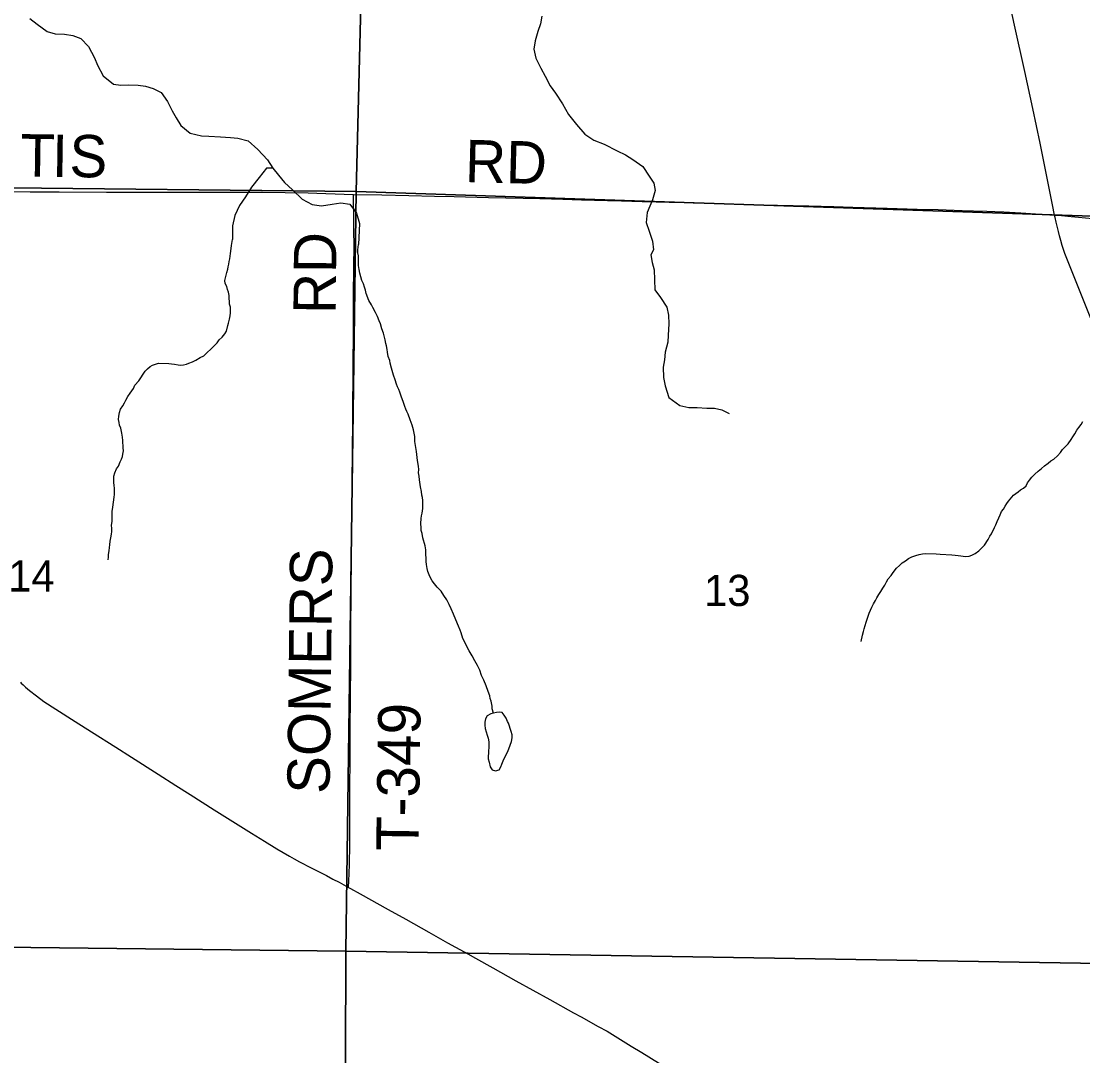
# Model space of a CAD drawing. Extents: x -8.8 to 41.4, y 0 to 34.6.
# Drawn here: x 3.891 to 5.315, y 15.426 to 16.815 of the extents above; entities that cross this region are included whole.
import ezdxf

# ---------------------------------------------------------------- set-up
doc = ezdxf.new("R2010")
doc.units = 0
for name, color, linetype in [('GM_X_Corporation', 7, 'Continuous'), ('GM_X_County_Road', 7, 'Continuous'), ('GM_X_Minor_Lake', 7, 'Continuous'), ('GM_X_Minor_River', 7, 'Continuous'), ('GM_X_Section_Text', 7, 'Continuous'), ('GM_X_Township_Road', 7, 'Continuous'), ('GM_X_Township_Road_Text', 7, 'Continuous'), ('GM_X_Township_Text', 7, 'Continuous')]:
    doc.layers.add(name, color=color, linetype=linetype)

msp = doc.modelspace()

# ---------------------------------------------------------------- linework, layer by layer
at = {"layer": 'GM_X_Corporation'}
for points in [[(3.3365, 17.5869), (4.3651, 17.5696), (4.3404, 16.586), (3.3269, 16.5968)], [(5.3707, 17.5614), (5.354, 16.5519), (4.3404, 16.586), (4.3651, 17.5696)], [(3.3269, 16.5968), (4.3404, 16.586), (4.3264, 15.5667), (3.3275, 15.5783)], [(4.3404, 16.586), (5.354, 16.5519), (5.3394, 15.5503), (4.3264, 15.5667)], [(4.3264, 15.5667), (4.3237, 14.5538), (3.3268, 14.5649), (3.3275, 15.5783)], [(4.3264, 15.5667), (5.3394, 15.5503), (5.3392, 15.4586), (5.3337, 14.5401), (4.3237, 14.5538)]]:
    msp.add_lwpolyline(points, close=True, dxfattribs=at)
at = {"layer": 'GM_X_County_Road'}
for points in [[(5.332, 16.4001), (5.2912, 16.5029), (5.2875, 16.5136), (5.2856, 16.5202), (5.2839, 16.5266), (5.2824, 16.5325), (5.2811, 16.5379), (5.2795, 16.5447), (5.278, 16.5511), (5.2773, 16.5543), (5.2745, 16.5684), (5.2578, 16.6509), (5.2482, 16.6973), (5.2372, 16.7472), (5.2236, 16.8095), (5.2113, 16.8654)], [(3.8697, 16.5859), (3.9034, 16.5858), (3.9419, 16.5857), (4.0058, 16.5853), (4.0326, 16.5853), (4.0679, 16.5854), (4.1058, 16.5853), (4.1306, 16.5853), (4.1561, 16.5853), (4.1694, 16.5854), (4.1846, 16.5853), (4.2144, 16.5851), (4.2759, 16.5841), (4.2877, 16.5837), (4.3243, 16.5825), (4.3369, 16.5822), (4.3747, 16.5815), (4.4113, 16.5808), (4.4454, 16.58), (4.4721, 16.5793), (4.487, 16.5791), (4.5181, 16.578), (4.5647, 16.577), (4.587, 16.5765), (4.6175, 16.5757), (4.6429, 16.575), (4.6777, 16.5741), (4.6963, 16.5737), (4.7242, 16.5728), (4.7429, 16.5722), (4.7603, 16.5718), (4.7832, 16.5711), (4.7926, 16.5709), (4.818, 16.5703), (4.8646, 16.5688), (4.9056, 16.5677), (4.9478, 16.5667), (4.9814, 16.5658), (5.0068, 16.5651), (5.0528, 16.5637), (5.0931, 16.5625), (5.1211, 16.5617), (5.1534, 16.5606), (5.1684, 16.5601), (5.1863, 16.5598), (5.1973, 16.5594), (5.2092, 16.5589), (5.232, 16.5574), (5.2585, 16.5557), (5.2773, 16.5543), (5.2867, 16.5537), (5.2997, 16.5526), (5.3096, 16.5517), (5.328, 16.55)], [(3.8901, 15.9275), (3.8913, 15.9263), (3.8936, 15.9241), (3.897, 15.9211), (3.9024, 15.9164), (3.9117, 15.9092), (3.9217, 15.9019), (3.9377, 15.8913), (3.9634, 15.8749), (3.9854, 15.8609), (4.018, 15.8403), (4.0389, 15.8269), (4.0751, 15.804), (4.0987, 15.7889), (4.1176, 15.7769), (4.1502, 15.7564), (4.2002, 15.7251), (4.2176, 15.7142), (4.2339, 15.7041), (4.251, 15.6941), (4.2575, 15.6904), (4.2646, 15.6866), (4.28, 15.6785), (4.2883, 15.6743), (4.3005, 15.668), (4.3093, 15.6634), (4.3175, 15.6591), (4.3303, 15.6523), (4.3329, 15.6509), (4.346, 15.6438), (4.3834, 15.6228), (4.4072, 15.6094), (4.4381, 15.592), (4.463, 15.578), (4.4901, 15.5629), (4.5005, 15.5572), (4.5238, 15.5442), (4.5548, 15.527), (4.6004, 15.5016), (4.6319, 15.4841), (4.6422, 15.4785), (4.6651, 15.4658), (4.677, 15.4591), (4.7093, 15.4393), (4.7236, 15.4306), (4.7592, 15.4089)]]:
    msp.add_lwpolyline(points, dxfattribs=at)
at = {"layer": 'GM_X_Minor_Lake'}
for points in [[(4.5363, 15.8871), (4.5331, 15.8874), (4.5286, 15.8868), (4.5248, 15.8861), (4.5209, 15.8851), (4.5163, 15.8826), (4.5139, 15.8785), (4.513, 15.8739), (4.5129, 15.8698), (4.5136, 15.8656), (4.5163, 15.8564), (4.5174, 15.8525), (4.5184, 15.8476), (4.5186, 15.8434), (4.5185, 15.8396), (4.518, 15.8358), (4.5177, 15.8248), (4.5187, 15.8202), (4.5204, 15.8141), (4.523, 15.8102), (4.5275, 15.8086), (4.5325, 15.8099), (4.5345, 15.8141), (4.5357, 15.8178), (4.5377, 15.8219), (4.5394, 15.8261), (4.5434, 15.8336), (4.5454, 15.8384), (4.5471, 15.843), (4.5487, 15.8482), (4.5496, 15.8531), (4.5497, 15.8569), (4.5484, 15.8614), (4.5447, 15.8727)], [(4.5447, 15.8727), (4.5434, 15.875), (4.5416, 15.8792), (4.5391, 15.8835), (4.5363, 15.8871)]]:
    msp.add_lwpolyline(points, dxfattribs=at)
at = {"layer": 'GM_X_Minor_River'}
for points in [[(3.9029, 16.8182), (3.9126, 16.8108), (3.926, 16.8006), (3.9366, 16.7977), (3.9494, 16.797), (3.9604, 16.7952), (3.9713, 16.7915), (3.9813, 16.7806), (3.9896, 16.7656), (3.9935, 16.7557), (4.0011, 16.7411), (4.0149, 16.7301), (4.0247, 16.7288), (4.0354, 16.7293), (4.0479, 16.7286), (4.0577, 16.7272), (4.0682, 16.7243), (4.0787, 16.7191), (4.0872, 16.7067), (4.0937, 16.6945), (4.0991, 16.6848), (4.1053, 16.6748), (4.118, 16.6643), (4.133, 16.6609), (4.1429, 16.6603), (4.1584, 16.6595), (4.1717, 16.6584), (4.1819, 16.6578), (4.1955, 16.654), (4.2088, 16.6423), (4.2214, 16.6284), (4.2287, 16.6176), (4.2364, 16.6079), (4.2445, 16.5982), (4.2549, 16.5881), (4.2679, 16.576), (4.2813, 16.5685), (4.2942, 16.5667), (4.3083, 16.569), (4.3201, 16.571), (4.3322, 16.5691), (4.341, 16.5568), (4.3448, 16.543), (4.3438, 16.5148)], [(4.5895, 16.8215), (4.5878, 16.8109), (4.5841, 16.8008), (4.5804, 16.7883), (4.579, 16.777), (4.5813, 16.7648), (4.5882, 16.7514), (4.594, 16.741), (4.6005, 16.7279), (4.6078, 16.7179), (4.6173, 16.7036), (4.6253, 16.6894), (4.636, 16.6759), (4.6474, 16.6631), (4.6594, 16.6548), (4.6733, 16.6495), (4.6905, 16.6408), (4.7017, 16.6352), (4.7114, 16.6289), (4.7249, 16.6198), (4.7336, 16.6067), (4.7398, 16.5971), (4.7415, 16.5872), (4.7382, 16.5747), (4.7309, 16.5579), (4.7294, 16.5446), (4.7333, 16.5328), (4.7379, 16.5194), (4.7391, 16.508)], [(4.2287, 16.6176), (4.2203, 16.6174), (4.2102, 16.6047), (4.2, 16.5917), (4.1921, 16.579), (4.1842, 16.5671), (4.1778, 16.554), (4.1744, 16.54), (4.1744, 16.5218)], [(4.1729, 16.5097), (4.1734, 16.5135), (4.1744, 16.5218)], [(4.0078, 16.0918), (4.0082, 16.0956), (4.0083, 16.099), (4.0092, 16.1039), (4.0097, 16.1085), (4.0102, 16.1119), (4.0107, 16.1168), (4.0116, 16.1214), (4.0122, 16.1263), (4.0126, 16.1297), (4.0127, 16.1339), (4.0125, 16.1381), (4.013, 16.1434), (4.0133, 16.1532), (4.0134, 16.1566), (4.0143, 16.1623), (4.0158, 16.176), (4.0163, 16.1794), (4.0165, 16.1877), (4.0159, 16.1919), (4.0156, 16.1953), (4.0154, 16.1995), (4.0155, 16.2041), (4.0168, 16.2086), (4.0192, 16.2139), (4.0216, 16.2176), (4.024, 16.2232), (4.0256, 16.227), (4.0269, 16.2304), (4.0277, 16.2338), (4.0282, 16.2379), (4.028, 16.2421), (4.0275, 16.252), (4.0272, 16.2562), (4.0262, 16.2619), (4.0249, 16.2684), (4.0231, 16.2726), (4.0225, 16.2761), (4.0218, 16.2803), (4.022, 16.2848), (4.0229, 16.2894), (4.0245, 16.2939), (4.0273, 16.2984), (4.0297, 16.3025), (4.0313, 16.3059), (4.0341, 16.3111), (4.0373, 16.3156), (4.0416, 16.3215), (4.0436, 16.326), (4.0491, 16.3319), (4.0574, 16.345), (4.0606, 16.3483), (4.0641, 16.3513), (4.0675, 16.3531), (4.0714, 16.3545), (4.0752, 16.3555), (4.0892, 16.3551), (4.0926, 16.3547), (4.0968, 16.3542), (4.1017, 16.3533), (4.1051, 16.3532), (4.1089, 16.3534), (4.1127, 16.3545), (4.1162, 16.3555), (4.1208, 16.3573), (4.1254, 16.3598), (4.1312, 16.3631), (4.1362, 16.3656), (4.1502, 16.3789), (4.1541, 16.3829), (4.1565, 16.3871), (4.1608, 16.3907), (4.1643, 16.3952), (4.1667, 16.3986), (4.1684, 16.4061), (4.1693, 16.4095), (4.1706, 16.4148), (4.1715, 16.4193), (4.172, 16.4231), (4.1721, 16.4265), (4.1718, 16.4307), (4.1708, 16.4349), (4.1705, 16.4387), (4.1702, 16.4421), (4.17, 16.4467), (4.1693, 16.4509), (4.1679, 16.4544), (4.1669, 16.4586), (4.1647, 16.4624), (4.1641, 16.4666), (4.1653, 16.4704), (4.1662, 16.4738), (4.1671, 16.4776), (4.1683, 16.4817), (4.1688, 16.4851), (4.1696, 16.4885), (4.1701, 16.4923), (4.171, 16.4957), (4.1715, 16.4991), (4.172, 16.5029), (4.1729, 16.5097)], [(4.3609, 16.4341), (4.3576, 16.4399), (4.3541, 16.4491), (4.3531, 16.4537), (4.3517, 16.4576), (4.3503, 16.4622), (4.3481, 16.4668), (4.3467, 16.4714), (4.3454, 16.4767), (4.3447, 16.4813), (4.3438, 16.4867), (4.3435, 16.4927), (4.3436, 16.4962), (4.3434, 16.4996), (4.3427, 16.5038), (4.3428, 16.5076), (4.3433, 16.5114), (4.3438, 16.5148)], [(4.7391, 16.508), (4.7358, 16.5011), (4.7377, 16.4908), (4.7401, 16.4808), (4.7408, 16.4675), (4.7412, 16.4542), (4.7489, 16.4437), (4.7572, 16.4309), (4.7595, 16.4199), (4.7599, 16.4085), (4.7591, 16.3933), (4.7584, 16.3838), (4.755, 16.3703), (4.7539, 16.36), (4.7525, 16.3502), (4.7529, 16.3365), (4.7548, 16.3251), (4.76, 16.3097), (4.7745, 16.299), (4.7869, 16.2964), (4.7979, 16.2961), (4.8108, 16.2953), (4.8211, 16.2954), (4.8309, 16.2932), (4.841, 16.2883)], [(4.5248, 15.8861), (4.523, 15.8919), (4.5227, 15.8953), (4.5214, 15.9022), (4.5204, 15.9056), (4.5197, 15.9091), (4.5176, 15.9152), (4.5148, 15.9225), (4.5116, 15.9302), (4.5087, 15.9368), (4.5063, 15.9437), (4.5031, 15.9502), (4.4998, 15.9564), (4.4962, 15.9629), (4.4922, 15.9695), (4.489, 15.9753), (4.4861, 15.9815), (4.4836, 15.9861), (4.4812, 15.9938), (4.4801, 15.9972), (4.4776, 16.0026), (4.4741, 16.0111), (4.4712, 16.0191), (4.468, 16.0261), (4.4652, 16.0318), (4.4619, 16.038), (4.4583, 16.0438), (4.4543, 16.0496), (4.4491, 16.0551), (4.4455, 16.0597), (4.4425, 16.0636), (4.4404, 16.0675), (4.4386, 16.0717), (4.4364, 16.0763), (4.4358, 16.0802), (4.4348, 16.0855), (4.4345, 16.0897), (4.4343, 16.0931), (4.4341, 16.1), (4.4339, 16.1053), (4.4329, 16.1106), (4.4301, 16.1214), (4.4288, 16.1271), (4.4278, 16.1313), (4.4275, 16.1347), (4.4273, 16.1404), (4.4278, 16.1473), (4.4283, 16.1507), (4.4288, 16.1544), (4.4297, 16.1605), (4.4299, 16.1658), (4.4297, 16.1715), (4.4294, 16.1753), (4.4287, 16.1788), (4.4281, 16.1833), (4.4268, 16.1898), (4.4255, 16.199), (4.4249, 16.204), (4.4243, 16.2085), (4.4244, 16.2131), (4.4241, 16.2177), (4.4228, 16.2253), (4.4219, 16.2333), (4.4213, 16.2371), (4.4207, 16.2425), (4.4194, 16.2505), (4.4192, 16.2573), (4.4182, 16.2619), (4.4175, 16.2661), (4.4155, 16.2726), (4.413, 16.2795), (4.4102, 16.2872), (4.4084, 16.2907), (4.407, 16.2941), (4.4059, 16.2976), (4.4035, 16.3041), (4.4013, 16.3103), (4.3989, 16.3168), (4.3975, 16.3202), (4.396, 16.3241), (4.3946, 16.3275), (4.3929, 16.3333), (4.3904, 16.3398), (4.3877, 16.349), (4.3863, 16.3555), (4.3857, 16.3593), (4.3835, 16.3647), (4.3826, 16.3704), (4.3819, 16.3739), (4.3813, 16.3788), (4.3802, 16.3823), (4.3793, 16.3872), (4.3786, 16.3907), (4.3772, 16.396), (4.3751, 16.4018), (4.373, 16.4087), (4.3712, 16.4125), (4.3691, 16.4183), (4.3666, 16.4237), (4.363, 16.4306), (4.3609, 16.4341)], [(5.0181, 15.9824), (5.0198, 15.9908), (5.0211, 15.9957), (5.022, 15.9991), (5.0245, 16.0081), (5.0261, 16.0122), (5.0274, 16.016), (5.0286, 16.0201), (5.0303, 16.0243), (5.0323, 16.0284), (5.0343, 16.0329), (5.0371, 16.0374), (5.0391, 16.0407), (5.0415, 16.0452), (5.0443, 16.0493), (5.0471, 16.0538), (5.0495, 16.0579), (5.0519, 16.0624), (5.0542, 16.0665), (5.0582, 16.0706), (5.0606, 16.0747), (5.0653, 16.0807), (5.0692, 16.0844), (5.0731, 16.0877), (5.0773, 16.0906), (5.0812, 16.0935), (5.0858, 16.0957), (5.0912, 16.0974), (5.0958, 16.0988), (5.1003, 16.0998), (5.1038, 16.1001), (5.1186, 16.0997), (5.1239, 16.0992), (5.1394, 16.0987), (5.1439, 16.0982), (5.1481, 16.0977), (5.1583, 16.0963), (5.1629, 16.0969), (5.1663, 16.098), (5.1709, 16.1005), (5.1756, 16.1038), (5.1787, 16.1071), (5.1834, 16.1115), (5.1882, 16.119), (5.1906, 16.1235), (5.1926, 16.1269), (5.1966, 16.1351), (5.1986, 16.1389), (5.2002, 16.1434), (5.2026, 16.1482), (5.2043, 16.152), (5.2063, 16.1565), (5.2087, 16.1598), (5.2111, 16.164), (5.2131, 16.1673), (5.2154, 16.1707), (5.2221, 16.1785), (5.2283, 16.1832), (5.2318, 16.1858), (5.2356, 16.188), (5.2391, 16.1909), (5.2412, 16.195), (5.2435, 16.1988), (5.2467, 16.2029), (5.251, 16.2069), (5.2553, 16.211), (5.2599, 16.2143), (5.2638, 16.2179), (5.2685, 16.2216), (5.2723, 16.2245), (5.2762, 16.2271), (5.2813, 16.2315), (5.2852, 16.236), (5.288, 16.2397), (5.2919, 16.2438), (5.2954, 16.2475), (5.2997, 16.2534), (5.3017, 16.2568), (5.3045, 16.2609), (5.3073, 16.2657), (5.3097, 16.2695), (5.3128, 16.2736), (5.3152, 16.2773)]]:
    msp.add_lwpolyline(points, dxfattribs=at)
at = {"layer": 'GM_X_Township_Road'}
msp.add_lwpolyline([(4.3303, 15.6523), (4.3308, 15.6616), (4.3313, 15.6704), (4.3316, 15.684), (4.3318, 15.7089), (4.3318, 15.7592), (4.3319, 15.7772), (4.3321, 15.7946), (4.3323, 15.8145), (4.3324, 15.8312), (4.3325, 15.8523), (4.3326, 15.8691), (4.3329, 15.9033), (4.3333, 15.9548), (4.3333, 15.9654), (4.3334, 15.9797), (4.3335, 16.0113), (4.3338, 16.0349), (4.334, 16.0616), (4.3341, 16.0809), (4.3343, 16.1076), (4.3346, 16.1362), (4.3348, 16.1486), (4.3351, 16.1939), (4.3357, 16.2393), (4.336, 16.2766), (4.3361, 16.3058), (4.3363, 16.3306), (4.3365, 16.3498), (4.3368, 16.4002), (4.3368, 16.407), (4.3369, 16.4262), (4.337, 16.4417), (4.3375, 16.4889), (4.3376, 16.5094), (4.3375, 16.5377), (4.3374, 16.5551), (4.3371, 16.5725), (4.3369, 16.5822)], dxfattribs=at)

# ---------------------------------------------------------------- texts
at = {"layer": 'GM_X_Section_Text'}
for s, rotation, p in [('RD', 89.5059, (4.3131, 16.4216)), ('SOMERS', 89.3118, (4.3048, 15.7775)), ('T-349', 89.1574, (4.4241, 15.7008))]:
    msp.add_text(s, height=0.05682, rotation=rotation, dxfattribs=at).set_placement(p)
at = {"layer": 'GM_X_Township_Road_Text'}
for s, height, rotation, p in [('T', 0.0568, 359.1824, (3.8897, 16.6064)), ('I', 0.0568, 359.1855, (3.9322, 16.6058)), ('S', 0.0568, 359.1827, (3.9556, 16.6055)), ('RD', 0.05682, 358.5184, (4.486, 16.5988))]:
    msp.add_text(s, height=height, rotation=rotation, dxfattribs=at).set_placement(p)
at = {"layer": 'GM_X_Township_Text'}
for s, p in [('14', (3.8738, 16.0493)), ('13', (4.8071, 16.0298))]:
    msp.add_text(s, height=0.04186, rotation=0, dxfattribs=at).set_placement(p)

doc.saveas('drawing.dxf')
